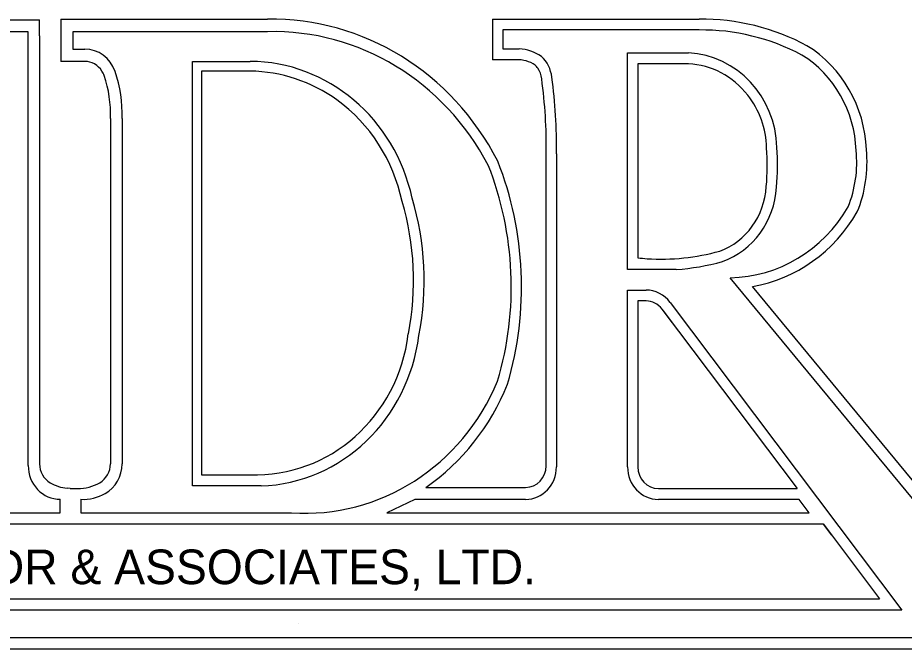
# Model space of a CAD drawing. Extents: x -59.3 to 34, y -1.2 to 22.
# Drawn here: x 32.49 to 33.31, y 3.477 to 4.06 of the extents above; entities that cross this region are included whole.
import ezdxf

# ---------------------------------------------------------------- set-up
doc = ezdxf.new("R2010")
doc.units = 0
doc.layers.add('RD_P_Text', color=7, linetype='Continuous')

msp = doc.modelspace()

# ---------------------------------------------------------------- linework, layer by layer
at = {"layer": 'RD_P_Text'}
for p, q in [((32.43408, 4.05843), (32.51008, 4.05843)), ((32.51008, 4.04345), (32.51008, 4.05843)), ((32.52996, 4.059), (32.52996, 4.02001)), ((32.52996, 4.059), (32.72096, 4.059)), ((32.92896, 4.059), (32.92896, 4.02146)), ((32.92896, 4.059), (33.11996, 4.059)), ((32.92896, 4.059), (32.92896, 4.02146)), ((32.92896, 4.059), (33.11996, 4.059)), ((32.51008, 4.04345), (32.51008, 3.64811)), ((32.54419, 4.02001), (32.52996, 4.02001)), ((32.55198, 4.02001), (32.54419, 4.02001)), ((32.94319, 4.02146), (32.92896, 4.02146)), ((32.94319, 4.02146), (32.92896, 4.02146)), ((32.95098, 4.02146), (32.94319, 4.02146)), ((32.70486, 4.01101), (32.65976, 4.01101)), ((32.65976, 4.01101), (32.65976, 3.63792)), ((32.57566, 3.96729), (32.57566, 3.64811)), ((32.97852, 3.64621), (32.97852, 3.93474)), ((33.38489, 3.55057), (33.16923, 3.81191)), ((33.08681, 3.78957), (33.2106, 3.62519)), ((32.65976, 3.63792), (32.66831, 3.63792)), ((32.66831, 3.63792), (32.70486, 3.63792)), ((32.53838, 3.62516), (32.53558, 3.62542)), ((32.53838, 3.62516), (32.53558, 3.62542)), ((32.53838, 3.62516), (32.54534, 3.62516)), ((32.86732, 3.62621), (32.95952, 3.62621)), ((33.08223, 3.62519), (33.2106, 3.62519)), ((33.23507, 3.59224), (33.28673, 3.52336)), ((32.21118, 3.52336), (33.28673, 3.52336)), ((32.75, 3.5), (32.75, 3.5)), ((33.44039, 3.47664), (32.07007, 3.47664))]:
    msp.add_line(p, q, dxfattribs=at)
for points in [[(32.49963, 3.64634), (32.49963, 4.04743), (32.43976, 4.04743), (32.13412, 3.55203)], [(32.72096, 4.04743), (32.54097, 4.04743), (32.54097, 4.03132), (32.55198, 4.03132)], [(33.11996, 4.049), (32.93846, 4.049), (32.93846, 4.03146), (32.95356, 4.03146)], [(33.05373, 4.02776), (33.11024, 4.02776)], [(33.09871, 3.82764), (33.05373, 3.82764), (33.05373, 4.02776)], [(32.65139, 3.62757), (32.65139, 4.02001), (32.70486, 4.02001)], [(33.11001, 4.01776), (33.06323, 4.01776), (33.06323, 3.83841)], [(32.58641, 3.96729), (32.58641, 3.96683), (32.58641, 3.64811)], [(32.98802, 3.93464), (32.98802, 3.64519)], [(33.37719, 3.54313), (33.14872, 3.82)], [(33.05373, 3.64519), (33.05373, 3.80857), (33.07085, 3.80857)], [(33.09319, 3.79721), (33.30749, 3.51264), (32.20382, 3.51264)], [(33.07085, 3.79857), (33.06323, 3.79857), (33.06323, 3.64519)], [(33.09537, 3.77821), (33.08574, 3.791)], [(32.71502, 3.62757), (32.65139, 3.62757)], [(32.86732, 3.62621), (32.88937, 3.62621)], [(33.08223, 3.62519), (33.08603, 3.62519)], [(32.41176, 3.61524), (32.2551, 3.61524), (32.24762, 3.60274), (32.5292, 3.60274), (32.5292, 3.61524)], [(32.54836, 3.61524), (32.54836, 3.60274), (32.74315, 3.60274)], [(32.95952, 3.61519), (32.85698, 3.61519), (32.83108, 3.60274), (33.22168, 3.60274), (33.21235, 3.61519), (33.08223, 3.61519)], [(33.24257, 3.58224), (33.23507, 3.59224), (32.24118, 3.59224), (32.20224, 3.52719)], [(32.06602, 3.50059), (32.06602, 3.48764), (33.42994, 3.48764), (33.42994, 3.50061)]]:
    msp.add_lwpolyline(points, dxfattribs=at)
for centre, major_axis, start_param, end_param in [((32.72433, 3.80818), (0, 0.25085), 5.209873, 6.297313), ((33.12226, 3.8329), (0, 0.22611), 5.810103, 6.294452), ((33.12226, 3.8329), (0, 0.22611), 5.810103, 6.294452), ((32.72602, 3.80812), (0, 0.23937), 5.218006, 6.305445), ((33.12243, 3.83351), (0, 0.21551), 5.814829, 6.29527), ((33.16379, 3.93362), (0, 0.11672), 4.753214, 5.755325), ((33.16379, 3.93362), (0, 0.11672), 4.753214, 5.755325), ((32.55198, 4.00001), (0, 0.03131), 5.060756, 6.283185), ((32.95218, 3.98966), (0, 0.04182), 5.696071, 6.248499), ((33.10631, 3.93781), (0, 0.09005), 4.740194, 6.23721), ((33.16379, 3.93362), (0, 0.10672), 4.750292, 5.755325), ((32.55198, 4.00001), (0, 0.02), 5.294753, 6.283185), ((32.70388, 3.8572), (0, 0.16282), 4.938334, 6.276888), ((32.95218, 3.98966), (0, 0.03182), 5.717883, 6.322951), ((32.95511, 4.00164), (0, 0.02041), 5.34604, 5.529903), ((32.95511, 4.00164), (0, 0.03041), 4.832872, 5.561833), ((33.10631, 3.93781), (0, 0.08005), 5.402738, 6.234422), ((32.55198, 4.00001), (0, 0.02), 5.060756, 5.294753), ((32.47755, 3.97156), (0, 0.11467), 4.675194, 5.060756), ((32.70276, 3.85737), (0, 0.15366), 5.684676, 6.268828), ((32.95511, 4.00164), (0, 0.02041), 4.827568, 5.34604), ((32.95511, 4.00164), (0, 0.02041), 4.827568, 5.34604), ((32.47755, 3.97156), (0, 0.10336), 4.671123, 5.060756), ((32.57484, 3.94271), (0, 0.425), 4.693619, 4.857063), ((32.57484, 3.94271), (0, 0.425), 4.693619, 4.857063), ((32.57484, 3.94271), (0, 0.435), 4.693836, 4.856756), ((32.70276, 3.85737), (0, 0.15366), 4.930275, 5.684676), ((33.10631, 3.93781), (0, 0.08005), 4.740194, 5.402738), ((33.10631, 3.93781), (0, 0.08005), 4.740194, 5.402738), ((33.00347, 3.92393), (0, 0.18895), 4.608112, 4.797709), ((33.00347, 3.92393), (0, 0.18895), 4.608112, 4.797709), ((33.00861, 3.92385), (0, 0.19356), 4.607961, 4.797558), ((33.16601, 3.92655), (0, 0.10489), 4.309756, 4.818512), ((33.16601, 3.92655), (0, 0.11489), 4.303317, 4.815541), ((33.16601, 3.92655), (0, 0.11489), 4.303317, 4.815541), ((32.66751, 3.81165), (0, 0.3034), 4.410917, 5.105556), ((32.66751, 3.81165), (0, 0.2934), 4.410917, 5.105556), ((33.11824, 3.90826), (0, -0.06723), 0.330696, 1.511334), ((33.11824, 3.90826), (0, -0.06723), 0.330696, 1.511334), ((33.11779, 3.90865), (0, -0.07773), 0.32607, 1.506707), ((32.62601, 3.8177), (0, 0.25236), 4.509144, 5.018206), ((32.62458, 3.81762), (0, 0.24352), 4.507644, 5.016706), ((33.14666, 3.95705), (0, -0.13706), 0.015856, 1.021186), ((33.14666, 3.95705), (0, -0.14706), 0.16231, 1.026165), ((33.14666, 3.95705), (0, -0.14706), 0.16231, 1.026165), ((33.08509, 4.05603), (0, -0.21884), 6.219099, 6.545404), ((33.08509, 4.05603), (0, -0.21884), 6.219099, 6.545404), ((33.08509, 4.05603), (0, -0.21884), 6.177822, 6.219099), ((33.08509, 4.05603), (0, -0.22884), 0.06267, 0.262218), ((33.07085, 3.77857), (0, 0.03), 5.382662, 6.283185), ((33.07085, 3.77857), (0, 0.02), 5.382662, 6.283185), ((32.70994, 3.78768), (0, -0.14986), 6.247489, 7.723), ((32.70994, 3.78768), (0, -0.16019), 0.033392, 1.439815), ((32.75571, 3.80698), (0, -0.20467), 6.218561, 7.439351), ((32.75561, 3.80484), (0, -0.21386), 0.582172, 1.170799), ((32.52908, 3.64811), (0, -0.02), 4.712389, 5.785309), ((32.55666, 3.64811), (0, -0.02), 0.497877, 1.570796), ((32.55666, 3.64811), (0, -0.03132), 0.497877, 1.570796), ((32.52918, 3.64634), (0, -0.0311), 4.712389, 6.28383), ((32.95952, 3.64621), (0, -0.02), 0, 1.570796), ((32.95952, 3.64519), (0, -0.03), 0, 1.570796), ((33.08223, 3.64519), (0, -0.03), 4.712389, 6.283185), ((33.08223, 3.64519), (0, -0.02), 4.712389, 6.283185), ((32.54013, 3.66951), (0, -0.04436), 5.785308, 6.174936), ((32.54561, 3.66951), (0, -0.04436), 6.276852, 6.781063), ((32.5506, 3.65985), (0, -0.04467), 6.230381, 6.780961)]:
    msp.add_ellipse(centre, major_axis=major_axis, ratio=0.95, start_param=start_param, end_param=end_param, dxfattribs=at)

# ---------------------------------------------------------------- texts
msp.add_text('ADR & ASSOCIATES, LTD.', height=0.0319999, dxfattribs=at).set_placement((32.43646, 3.5368))

doc.saveas('drawing.dxf')
